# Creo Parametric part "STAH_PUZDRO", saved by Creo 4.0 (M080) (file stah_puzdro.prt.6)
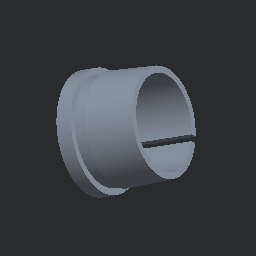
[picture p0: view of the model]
Units: millimeter Kilogram Sec (mmKs); MM, KILOGRAM, SECS
Materials in the file: OCEL_N

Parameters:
  MFG_WP_MATERIAL = "OCEL"
  NAZOV = "STAH_PUZDRO"
  PTC_MATERIAL_NAME = "OCEL_N"

Other parameters: HMOTNOST, HUSTOTA, D2, D1, D13

Created from: STAH_PUZDRA.PRT

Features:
  1. datum plane "DTM1"
  2. cut

Other named items: THRU

Layers: 1, 2, 3, 4, 5, 6, 7, 8, 9, 10, 11, 12, 13, 14, 15, 16, 17, 18, 19, 20, 21, 22, 23, 24, 25, 26, 27, 28, 29, 30, 31, 32

Family table entries: GENERIC, STAH_PUZDRO_AH308, STAH_PUZDRO, value(d_val), 2/D, 2/>, value(i_val), STAH_PUZDRO_AH2308, STAH_PUZDRO, 2/D, 2/D, STAH_PUZDRO_AH2309, STAH_PUZDRO, !/D, 2/I, 2/F, STAH_PUZDRO_AH310X, STAH_PUZDRO, 2/I, STAH_PUZDRO_AH2310X, STAH_PUZDRO, 2/I, 2/I, 2/ , STAH_PUZDRO_AH311X, STAH_PUZDRO, !/I, 2/N, STAH_PUZDRO_AH2311X, STAH_PUZDRO, !/I, 2/N, 2/K, 2/", STAH_PUZDRO_AH312X, STAH_PUZDRO, 2/N, 2/D, 2/ , STAH_PUZDRO_AH2312X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

Surfaces: 8 plane, 5 cylinder, 1 cone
